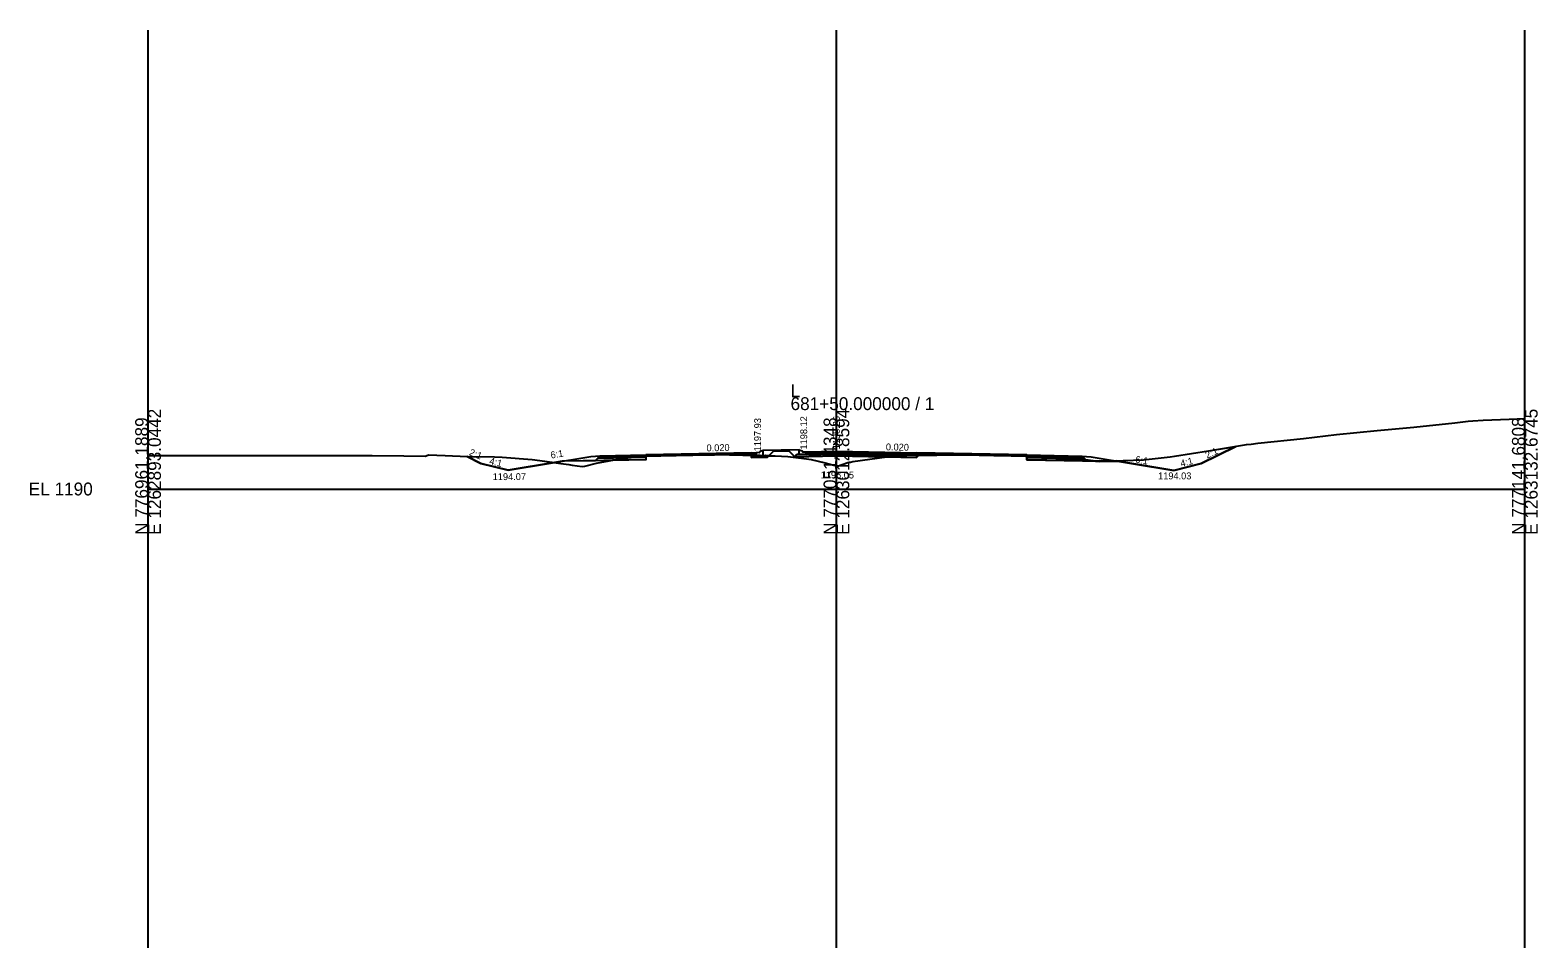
# Model space of a CAD drawing. Extents: x -41 to 1262860, y -100 to 777489.
# Drawn here: x 474.3 to 802.8, y 3845 to 4045 of the extents above; entities that cross this region are included whole.
import ezdxf

# ---------------------------------------------------------------- set-up
doc = ezdxf.new("R2010")
doc.units = 0
for name, color, linetype in [('Exist Cross Section Cell', 7, 'Continuous'), ('Exist XS Center Line Elevation Label', 7, 'Continuous'), ('Exist XS Ground Line', 7, 'Continuous'), ('Prop CMT Pvmt Course 1', 7, 'Continuous'), ('Prop CMT Pvmt Surface', 7, 'Continuous'), ('Prop CMT Shld Paved Course 1', 7, 'Continuous'), ('Prop CMT Shld Paved Course 2', 7, 'Continuous'), ('Prop CMT Shld Paved Course 4', 7, 'Continuous'), ('Prop CMT Subgrade Earthwork', 7, 'Continuous'), ('Prop Conc Curb and Gutter', 7, 'Continuous'), ('Prop Conc Island Cover', 7, 'Continuous'), ('Prop XS Ditch Standard Text', 7, 'Continuous'), ('Prop XS Earthwork Shape', 7, 'Continuous'), ('Prop XS Elevation Labels', 7, 'Continuous'), ('Prop XS Exc Vertical Line 1', 7, 'Continuous'), ('Prop XS Exc Vertical Line 2', 7, 'Continuous'), ('Prop XS Exc Vertical Line 3', 7, 'Continuous'), ('Prop XS Finish Grade', 7, 'Continuous'), ('Prop XS Hydro Elevations', 7, 'Continuous'), ('Prop XS SE Text', 7, 'Continuous'), ('Prop XS Side Slope Text', 7, 'Continuous'), ('Scratch_Level_4', 7, 'Continuous'), ('Scratch_Level_6', 7, 'Continuous')]:
    doc.layers.add(name, color=color, linetype=linetype)

msp = doc.modelspace()

# ---------------------------------------------------------------- linework, layer by layer
at = {"layer": 'Exist Cross Section Cell'}
for p, q in [((650, 3945), (650, 3965)), ((500, 3945), (650, 3945)), ((650, 3945), (800, 3945))]:
    msp.add_line(p, q, dxfattribs=at)
at = {"layer": 'Exist XS Ground Line'}
msp.add_lwpolyline([(500, 3952.28), (514.63, 3952.29), (516.29, 3952.3), (526.22, 3952.32), (533.63, 3952.3), (544.87, 3952.31), (548.86, 3952.31), (555.75, 3952.23), (560.48, 3952.16), (560.57, 3952.2), (561.14, 3952.48), (564.73, 3952.29), (569.58, 3952.07), (575.46, 3952), (577.13, 3951.95), (583.67, 3951.41), (585.35, 3951.23), (589.93, 3950.55), (591.69, 3950.31), (592.44, 3950.18), (594.6, 3949.88), (595.14, 3950), (597.7, 3950.61), (600.49, 3951.11), (603.14, 3951.62), (604.53, 3951.76), (607.37, 3952.11), (610.02, 3952.28), (610.86, 3952.34), (614.04, 3952.38), (623.41, 3952.5), (626.73, 3952.43), (635.44, 3952.26), (636.62, 3952.2), (639.4, 3952.07), (641.73, 3951.78), (641.85, 3951.76), (644.5, 3951.46), (647.58, 3950.69), (650.2, 3949.99), (652.51, 3950.77), (652.74, 3950.85), (653.05, 3950.87), (653.55, 3950.96), (661.47, 3952.07), (663.52, 3952.18), (665.31, 3952.27), (671.88, 3952.4), (677.76, 3952.5), (677.91, 3952.52), (684.28, 3952.35), (689.58, 3952.22), (691.3, 3952.12), (693.18, 3952.01), (697.2, 3951.78), (697.32, 3951.77), (700.17, 3951.59), (703.86, 3951.43), (707.35, 3950.97), (712.45, 3951.18), (716.88, 3951.37), (717.51, 3951.43), (722.69, 3951.98), (723.7, 3952.14), (731.07, 3953.31), (739.33, 3954.67), (740.34, 3954.79), (741.8, 3954.96), (751.75, 3956.02), (758.96, 3956.86), (767.8, 3957.73), (775.79, 3958.44), (784.75, 3959.43), (787.66, 3959.78), (788.64, 3959.87), (790.89, 3960.03), (796.59, 3960.23), (800, 3960.36)], dxfattribs=at)
at = {"layer": 'Prop CMT Pvmt Course 1'}
for p, q in [((631.5, 3952.64), (632.5, 3952.66)), ((632.5, 3952.91), (632.5, 3952.66)), ((643.37, 3953.13), (643.37, 3952.88)), ((643.37, 3952.88), (650, 3953.01)), ((650, 3953.01), (667.5, 3952.66))]:
    msp.add_line(p, q, dxfattribs=at)
for points in [[(608.5, 3952.43), (608.5, 3952.18), (631.5, 3952.64), (631.5, 3952.64), (631.5, 3952.89), (631.5, 3952.89), (631.5, 3952.89), (608.5, 3952.43), (608.5, 3952.43)], [(691.5, 3952.43), (691.5, 3952.43), (667.5, 3952.91), (667.5, 3952.91), (667.5, 3952.91), (667.5, 3952.66), (667.5, 3952.66), (691.5, 3952.18), (691.5, 3952.43)]]:
    msp.add_lwpolyline(points, dxfattribs=at)
at = {"layer": 'Prop CMT Pvmt Surface'}
for p, q in [((598.5, 3952.23), (608.5, 3952.43)), ((608.5, 3952.43), (631.5, 3952.89)), ((631.5, 3952.89), (632.5, 3952.91)), ((643.37, 3953.13), (650, 3953.26)), ((650, 3953.26), (667.5, 3952.91)), ((667.5, 3952.91), (691.5, 3952.43)), ((691.5, 3952.43), (703.5, 3952.19))]:
    msp.add_line(p, q, dxfattribs=at)
at = {"layer": 'Prop CMT Shld Paved Course 1'}
for p, q in [((604.5, 3952.35), (604.5, 3952.35)), ((608.5, 3952.43), (608.5, 3952.43)), ((608.5, 3952.43), (608.5, 3952.43)), ((608.5, 3952.43), (608.5, 3952.18)), ((691.5, 3952.43), (691.5, 3952.43)), ((691.5, 3952.43), (691.5, 3952.43)), ((691.5, 3952.43), (691.5, 3952.18)), ((695.5, 3952.35), (695.5, 3952.35)), ((598.24, 3951.98), (598.5, 3952.23)), ((608.5, 3952.18), (598.24, 3951.98)), ((608.5, 3952.18), (608.5, 3952.18)), ((691.5, 3952.18), (691.5, 3952.18)), ((691.5, 3952.18), (703.76, 3951.94)), ((703.76, 3951.94), (703.5, 3952.19))]:
    msp.add_line(p, q, dxfattribs=at)
at = {"layer": 'Prop CMT Shld Paved Course 2'}
for p, q in [((610.86, 3952.23), (614.04, 3952.29)), ((614.04, 3952.29), (610.86, 3952.23)), ((614.04, 3952.29), (623.41, 3952.48)), ((623.41, 3952.48), (614.04, 3952.29)), ((614.04, 3952.29), (614.04, 3952.29)), ((614.04, 3952.29), (614.04, 3952.29)), ((623.41, 3952.48), (626.73, 3952.55)), ((623.79, 3952.49), (623.41, 3952.48)), ((623.41, 3952.48), (623.41, 3952.48)), ((623.41, 3952.48), (623.41, 3952.48)), ((626.73, 3952.43), (623.79, 3952.49)), ((623.79, 3952.49), (623.79, 3952.49)), ((626.73, 3952.55), (631.5, 3952.64)), ((626.73, 3952.55), (626.73, 3952.55)), ((631.5, 3952.34), (626.73, 3952.43)), ((626.73, 3952.43), (626.73, 3952.43)), ((631.5, 3952.64), (631.5, 3952.64)), ((631.5, 3952.64), (631.5, 3952.64)), ((631.5, 3952.64), (631.5, 3952.51)), ((631.5, 3952.51), (631.5, 3952.51)), ((631.5, 3952.51), (631.5, 3952.34)), ((631.5, 3952.34), (631.5, 3952.31)), ((631.5, 3952.34), (631.5, 3952.34)), ((631.5, 3952.31), (632.5, 3952.33)), ((632.5, 3952.33), (632.5, 3952.66)), ((643.37, 3952.55), (643.37, 3952.88)), ((643.37, 3952.55), (650, 3952.68)), ((650, 3952.68), (667.5, 3952.33)), ((671.88, 3952.58), (667.5, 3952.66)), ((667.5, 3952.66), (667.5, 3952.66)), ((667.5, 3952.66), (667.5, 3952.33)), ((667.5, 3952.33), (667.5, 3952.33)), ((667.5, 3952.33), (667.93, 3952.32)), ((667.93, 3952.32), (671.88, 3952.4)), ((677.76, 3952.46), (671.88, 3952.58)), ((671.88, 3952.58), (671.88, 3952.58)), ((671.88, 3952.4), (676.56, 3952.48)), ((671.88, 3952.4), (671.88, 3952.4)), ((676.56, 3952.48), (676.56, 3952.48)), ((676.56, 3952.48), (677.76, 3952.46)), ((677.91, 3952.46), (677.76, 3952.46)), ((677.76, 3952.46), (677.76, 3952.46)), ((677.76, 3952.46), (677.76, 3952.46)), ((677.76, 3952.46), (677.91, 3952.46)), ((684.28, 3952.33), (677.91, 3952.46)), ((677.91, 3952.46), (684.28, 3952.33)), ((689.58, 3952.22), (684.28, 3952.33)), ((684.28, 3952.33), (684.28, 3952.33)), ((684.28, 3952.33), (684.28, 3952.33)), ((684.28, 3952.33), (689.58, 3952.22)), ((597.9, 3951.64), (598.24, 3951.98)), ((608.5, 3951.85), (597.9, 3951.64)), ((604.24, 3952.1), (604.24, 3952.1)), ((608.5, 3952.18), (610.02, 3952.21)), ((610.02, 3952.21), (608.5, 3952.18)), ((608.5, 3952.18), (608.5, 3952.18)), ((608.5, 3952.18), (608.5, 3952.18)), ((608.5, 3952.18), (608.5, 3951.85)), ((608.5, 3952.18), (608.5, 3952.18)), ((608.5, 3952.18), (608.5, 3952.18)), ((608.5, 3951.85), (608.5, 3951.85)), ((610.02, 3952.21), (610.86, 3952.23)), ((610.86, 3952.23), (610.02, 3952.21)), ((610.02, 3952.21), (610.02, 3952.21)), ((610.02, 3952.21), (610.02, 3952.21)), ((691.3, 3952.19), (689.58, 3952.22)), ((689.58, 3952.22), (689.58, 3952.22)), ((689.58, 3952.22), (689.58, 3952.22)), ((689.58, 3952.22), (689.58, 3952.22)), ((689.58, 3952.22), (689.58, 3952.22)), ((689.58, 3952.22), (689.58, 3952.22)), ((689.58, 3952.22), (689.58, 3952.22)), ((689.58, 3952.22), (691.3, 3952.12)), ((691.5, 3952.18), (691.3, 3952.19)), ((691.3, 3952.19), (691.3, 3952.19)), ((691.3, 3952.12), (691.3, 3952.12)), ((691.3, 3952.12), (691.5, 3952.11)), ((691.5, 3952.18), (691.5, 3952.18)), ((691.5, 3952.18), (691.5, 3952.18)), ((691.5, 3952.18), (691.5, 3951.85)), ((691.5, 3952.11), (691.5, 3952.18)), ((691.5, 3952.18), (691.5, 3952.18)), ((691.5, 3951.85), (691.5, 3951.85)), ((691.5, 3951.85), (704.1, 3951.6)), ((704.1, 3951.6), (703.76, 3951.94))]:
    msp.add_line(p, q, dxfattribs=at)
at = {"layer": 'Prop CMT Shld Paved Course 4'}
for p, q in [((631.5, 3952.31), (631.5, 3951.85)), ((632.5, 3952.33), (634.5, 3952.37)), ((634.5, 3952.37), (634.95, 3951.92)), ((641.37, 3952.51), (640.9, 3952.04)), ((643.37, 3952.55), (641.37, 3952.51)), ((667.5, 3952.33), (667.5, 3951.87)), ((667.93, 3952.32), (667.5, 3952.31)), ((597.44, 3951.17), (597.9, 3951.64)), ((608.5, 3951.39), (597.44, 3951.17)), ((603.4, 3951.75), (603.4, 3951.75)), ((603.9, 3951.76), (603.9, 3951.76)), ((608.5, 3951.85), (608.5, 3951.85)), ((608.5, 3951.85), (608.5, 3951.85)), ((608.5, 3951.85), (608.5, 3951.39)), ((631.5, 3951.85), (634.95, 3951.92)), ((643.37, 3952.09), (640.9, 3952.04)), ((643.37, 3952.09), (650, 3952.22)), ((650, 3952.22), (667.5, 3951.87)), ((691.5, 3951.85), (691.5, 3951.85)), ((691.5, 3951.85), (691.5, 3951.85)), ((691.5, 3951.85), (691.5, 3951.39)), ((691.5, 3951.39), (704.56, 3951.13)), ((704.56, 3951.13), (704.1, 3951.6))]:
    msp.add_line(p, q, dxfattribs=at)
at = {"layer": 'Prop CMT Subgrade Earthwork'}
for p, q in [((631.5, 3951.85), (631.5, 3952.34)), ((634.95, 3951.92), (636.44, 3953.41)), ((640.9, 3952.04), (639.48, 3953.47)), ((667.5, 3951.87), (667.5, 3952.31)), ((608.5, 3951.39), (590.22, 3951.03)), ((608.5, 3952.18), (608.5, 3951.39)), ((634.95, 3951.92), (631.5, 3951.85)), ((640.9, 3952.04), (650, 3952.22)), ((650, 3952.22), (667.5, 3951.87)), ((691.5, 3952.11), (691.5, 3951.39)), ((691.5, 3951.39), (711.78, 3950.99))]:
    msp.add_line(p, q, dxfattribs=at)
at = {"layer": 'Prop Conc Curb and Gutter'}
for p, q in [((633.19, 3952.93), (632.5, 3952.91)), ((632.5, 3952.33), (632.5, 3952.91)), ((632.5, 3952.33), (634, 3952.36)), ((633.25, 3953.01), (633.25, 3952.99)), ((634, 3953.36), (633.35, 3953.14)), ((634, 3952.36), (634, 3953.36)), ((641.87, 3953.51), (642.51, 3953.33)), ((641.87, 3952.52), (641.87, 3953.51)), ((643.37, 3952.55), (641.87, 3952.52)), ((642.62, 3953.19), (642.62, 3953.18)), ((642.68, 3953.12), (643.37, 3953.13)), ((643.37, 3952.55), (643.37, 3953.13))]:
    msp.add_line(p, q, dxfattribs=at)
for centre, radius, start, end in [((633.19, 3952.99), 0.0625, 271.1458, 360), ((633.4, 3953.01), 0.146, 108.435, 180), ((642.47, 3953.19), 0.146, 2.2915, 73.8566), ((642.68, 3953.18), 0.0625, 182.2915, 271.1458)]:
    msp.add_arc(centre, radius, start, end, dxfattribs=at)
at = {"layer": 'Prop Conc Island Cover'}
msp.add_line((641.87, 3953.51), (634, 3953.36), dxfattribs=at)
at = {"layer": 'Prop XS Earthwork Shape'}
for points in [[(634.95, 3951.92), (635.29, 3952.26), (631.5, 3952.34), (631.5, 3951.85)], [(635.44, 3952.26), (636.62, 3952.2), (639.4, 3952.07), (641.73, 3951.78), (641.85, 3951.76), (644.5, 3951.46), (647.58, 3950.69), (650.2, 3949.99), (652.51, 3950.77), (652.74, 3950.85), (653.05, 3950.87), (653.55, 3950.96), (660.98, 3952), (650, 3952.22), (640.9, 3952.04), (639.72, 3953.22), (636.18, 3953.15), (635.29, 3952.26)], [(667.5, 3951.87), (667.5, 3952.31), (665.31, 3952.27), (663.52, 3952.18), (661.47, 3952.07), (660.98, 3952)], [(731.07, 3953.31), (737.01, 3954.29), (729.5, 3950.53), (723.5, 3949.03), (711.78, 3950.99), (710.99, 3951.12), (712.45, 3951.18), (716.88, 3951.37), (717.51, 3951.43), (722.69, 3951.98), (723.7, 3952.14)], [(577.13, 3951.95), (583.67, 3951.41), (585.35, 3951.23), (588.57, 3950.75), (578.5, 3949.07), (572.5, 3950.57), (569.51, 3952.07), (569.58, 3952.07), (575.46, 3952)], [(588.57, 3950.75), (589.93, 3950.55), (591.69, 3950.31), (592.44, 3950.18), (594.6, 3949.88), (595.14, 3950), (597.7, 3950.61), (600.49, 3951.11), (601.19, 3951.25), (597.44, 3951.17), (590.22, 3951.03)], [(601.19, 3951.25), (603.14, 3951.62), (604.53, 3951.76), (607.37, 3952.11), (608.5, 3952.18), (608.5, 3951.39)], [(697.32, 3951.77), (700.17, 3951.59), (703.86, 3951.43), (704.33, 3951.37), (704.56, 3951.13), (691.5, 3951.39), (691.5, 3952.11), (693.18, 3952.01), (697.2, 3951.78)], [(704.56, 3951.13), (706.44, 3951.09), (704.33, 3951.37)], [(707.35, 3950.97), (709.04, 3951.04), (706.44, 3951.09)], [(709.04, 3951.04), (710.99, 3951.12), (711.78, 3950.99)]]:
    msp.add_lwpolyline(points, close=True, dxfattribs=at)
at = {"layer": 'Prop XS Exc Vertical Line 1'}
msp.add_line((500, 3845), (500, 4045), dxfattribs=at)
at = {"layer": 'Prop XS Exc Vertical Line 2'}
msp.add_line((650, 3845), (650, 4045), dxfattribs=at)
at = {"layer": 'Prop XS Exc Vertical Line 3'}
msp.add_line((800, 3845), (800, 4045), dxfattribs=at)
at = {"layer": 'Prop XS Finish Grade'}
for p, q in [((729.5, 3950.53), (737.01, 3954.29)), ((569.51, 3952.07), (572.5, 3950.57)), ((572.5, 3950.57), (578.5, 3949.07)), ((578.5, 3949.07), (596.5, 3952.07)), ((596.5, 3952.07), (598.5, 3952.23)), ((597.44, 3951.17), (598.5, 3952.23)), ((703.5, 3952.19), (705.5, 3952.03)), ((703.5, 3952.19), (704.56, 3951.13)), ((705.5, 3952.03), (723.5, 3949.03)), ((723.5, 3949.03), (729.5, 3950.53))]:
    msp.add_line(p, q, dxfattribs=at)
at = {"layer": 'Scratch_Level_4'}
msp.add_line((800, 3845), (800, 4045), dxfattribs=at)
at = {"layer": 'Scratch_Level_6'}
msp.add_line((500, 3845), (500, 4045), dxfattribs=at)

# ---------------------------------------------------------------- texts
at = {"layer": 'Exist Cross Section Cell'}
for s, p in [('L', (640, 3965)), ('681+50.000000 / 1', (640, 3962.2)), ('EL 1190', (474, 3943.6))]:
    msp.add_text(s, height=2.8, dxfattribs=at).set_placement(p)
for s, p in [('E 1262893.0442', (502.8, 3935)), ('E 1263012.8594', (652.8, 3935)), ('E 1263132.6745', (802.8, 3935)), ('N 776961.1889', (500, 3935)), ('N 777051.4348', (650, 3935)), ('N 777141.6808', (800, 3935))]:
    msp.add_text(s, height=2.8, rotation=90, dxfattribs=at).set_placement(p)
at = {"layer": 'Exist XS Center Line Elevation Label'}
msp.add_text('1195.05', height=1.5, dxfattribs=at).set_placement((646.57, 3947.3))
at = {"layer": 'Prop XS Ditch Standard Text'}
for s, p in [('1194.07', (575.1, 3946.94)), ('1194.03', (720.09, 3947.11))]:
    msp.add_text(s, height=1.5, dxfattribs=at).set_placement(p)
at = {"layer": 'Prop XS Elevation Labels'}
for s, p in [('1197.93', (633.57, 3953.2)), ('1198.12', (643.62, 3953.61))]:
    msp.add_text(s, height=1.5, rotation=90, dxfattribs=at).set_placement(p)
at = {"layer": 'Prop XS Hydro Elevations'}
msp.add_text('1198.26', height=1.5, rotation=90, dxfattribs=at).set_placement((650.74, 3953.66))
at = {"layer": 'Prop XS SE Text'}
for rotation, p in [(1.1458, (621.71, 3953.2)), (358.8542, (660.76, 3953.43))]:
    msp.add_text('0.020', height=1.5, rotation=rotation, dxfattribs=at).set_placement(p)
at = {"layer": 'Prop XS Side Slope Text'}
for s, rotation, p in [('2:1', 338.2726, (569.82, 3952.42)), ('6:1', 9.4623, (587.83, 3951.63)), ('2:1', 24.7387, (730.78, 3951.59)), ('4:1', 345.9638, (574.25, 3950.45)), ('6:1', 350.5377, (715.03, 3950.77)), ('4:1', 14.0362, (725.13, 3949.79))]:
    msp.add_text(s, height=1.5, rotation=rotation, dxfattribs=at).set_placement(p)

doc.saveas('drawing.dxf')
